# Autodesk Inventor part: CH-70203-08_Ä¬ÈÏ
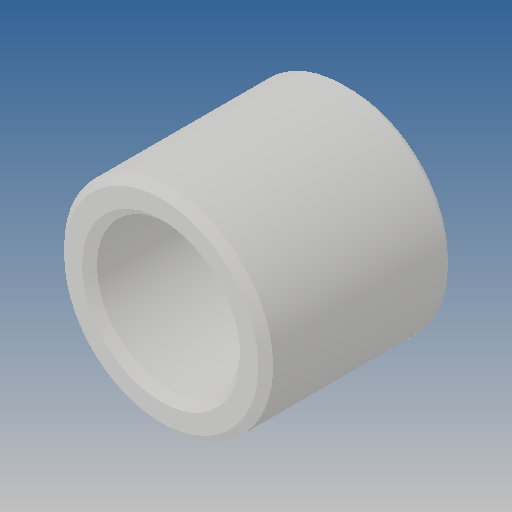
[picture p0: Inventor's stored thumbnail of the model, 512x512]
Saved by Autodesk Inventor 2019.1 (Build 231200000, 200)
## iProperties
Created: 2010-06
Part Number: CH-70203-08_Ä¬ÈÏ
Material: Ogólny
Document SubType Name: Modeling
Designer: CADENGINEERING4
Density: 1 g/cm^3
Appearance: Domyślna
Author: CADENGINEERING4
Revision Number: ÈÎºÎ
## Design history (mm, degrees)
feature "NONE"
node "Bryła1"
